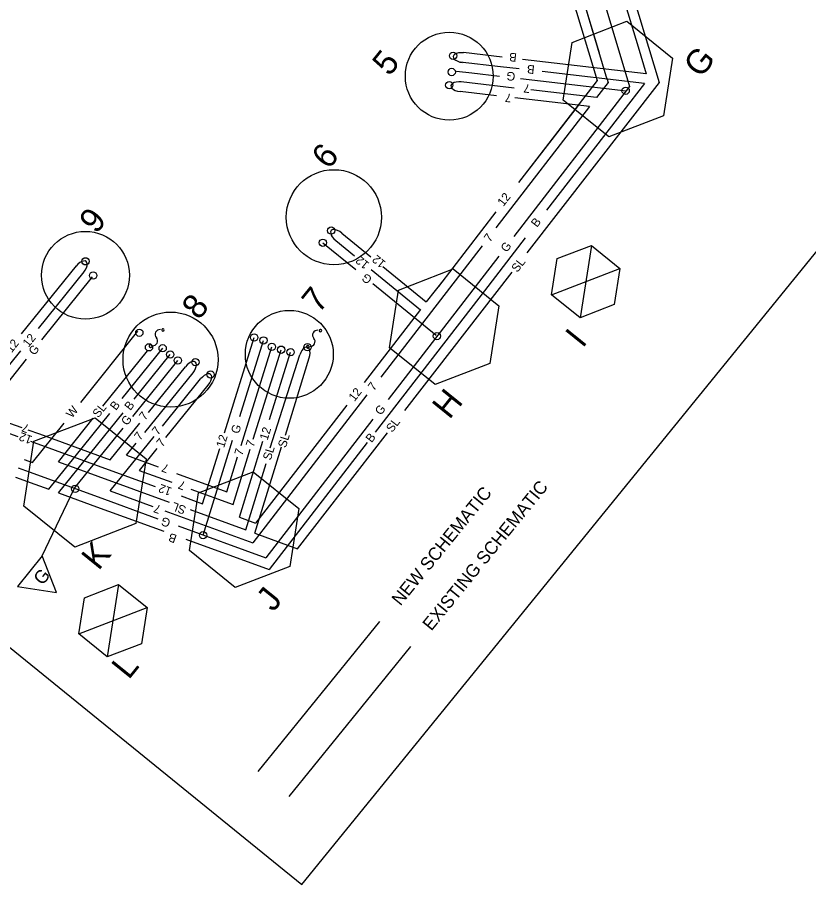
# Model space of a CAD drawing. Extents: x 592613 to 600223, y 4837996 to 4840103.
# Drawn here: x 592751.79 to 592782.58, y 4838886.03 to 4838919.81 of the extents above; entities that cross this region are included whole.
import ezdxf

# ---------------------------------------------------------------- set-up
doc = ezdxf.new("R2010")
doc.units = 0
for name, color, linetype in [('ENG_BORDER', 7, 'Continuous'), ('TCS_ELEC-CHAMBER-NEW', 7, 'Continuous'), ('TCS_FUSE', 7, 'Continuous'), ('TCS_PLATE', 7, 'Continuous'), ('TCS_POLE-NEW', 7, 'Continuous'), ('TCS_TX_LEGEND', 7, 'Continuous'), ('TCS_WR_12', 7, 'Continuous'), ('TCS_WR_7', 7, 'Continuous'), ('TCS_WR_B', 7, 'Continuous'), ('TCS_WR_G', 7, 'Continuous'), ('TCS_WR_SL', 7, 'Continuous'), ('TCS_WR_W', 7, 'Continuous'), ('TCS_WR_W-EXIST', 7, 'Continuous')]:
    doc.layers.add(name, color=color, linetype=linetype)

msp = doc.modelspace()

# ---------------------------------------------------------------- linework, layer by layer
at = {"layer": 'ENG_BORDER'}
for points in [[(592762.862, 4838886.033), (592888.241, 4839040.345), (592783.858, 4839125.156)], [(592658.479, 4838970.843), (592762.862, 4838886.033)]]:
    msp.add_lwpolyline(points, dxfattribs=at)
at = {"layer": 'TCS_ELEC-CHAMBER-NEW'}
for p, q in [((592773.377, 4838918.834), (592775.504, 4838919.654)), ((592775.504, 4838919.654), (592777.278, 4838918.222)), ((592773.023, 4838916.582), (592773.377, 4838918.834)), ((592777.278, 4838918.222), (592776.924, 4838915.969)), ((592774.797, 4838915.149), (592773.023, 4838916.582)), ((592776.924, 4838915.969), (592774.797, 4838915.149)), ((592772.794, 4838910.413), (592774.123, 4838910.925)), ((592774.123, 4838910.925), (592773.681, 4838908.11)), ((592774.123, 4838910.925), (592775.232, 4838910.03)), ((592772.573, 4838909.005), (592772.794, 4838910.413)), ((592766.624, 4838909.189), (592768.751, 4838910.009)), ((592768.751, 4838910.009), (592770.525, 4838908.577)), ((592772.573, 4838909.005), (592775.232, 4838910.03)), ((592775.232, 4838910.03), (592775.011, 4838908.622)), ((592766.27, 4838906.937), (592766.624, 4838909.189)), ((592773.681, 4838908.11), (592772.573, 4838909.005)), ((592770.525, 4838908.577), (592770.171, 4838906.324)), ((592775.011, 4838908.622), (592773.681, 4838908.11)), ((592768.044, 4838905.505), (592766.27, 4838906.937)), ((592770.171, 4838906.324), (592768.044, 4838905.505)), ((592752.432, 4838903.298), (592754.813, 4838904.216)), ((592754.813, 4838904.216), (592756.798, 4838902.613)), ((592752.036, 4838900.778), (592752.432, 4838903.298)), ((592756.798, 4838902.613), (592756.402, 4838900.092)), ((592758.84, 4838901.293), (592760.968, 4838902.113)), ((592760.968, 4838902.113), (592762.741, 4838900.681)), ((592758.487, 4838899.041), (592758.84, 4838901.293)), ((592754.021, 4838899.175), (592752.036, 4838900.778)), ((592762.741, 4838900.681), (592762.388, 4838898.428)), ((592756.402, 4838900.092), (592754.021, 4838899.175)), ((592760.26, 4838897.609), (592758.487, 4838899.041)), ((592762.388, 4838898.428), (592760.26, 4838897.609)), ((592754.397, 4838897.205), (592755.727, 4838897.717)), ((592755.727, 4838897.717), (592755.284, 4838894.902)), ((592755.727, 4838897.717), (592756.835, 4838896.822)), ((592754.176, 4838895.797), (592754.397, 4838897.205)), ((592754.176, 4838895.797), (592756.835, 4838896.822)), ((592756.835, 4838896.822), (592756.614, 4838895.414)), ((592755.284, 4838894.902), (592754.176, 4838895.797)), ((592756.614, 4838895.414), (592755.284, 4838894.902))]:
    msp.add_line(p, q, dxfattribs=at)
at = {"layer": 'TCS_FUSE'}
for centre, radius, start, end in [((592757.337, 4838907.46), 0.189, 85.1625, 221.8112), ((592757.452, 4838907.634), 0.0513, 44.5286, 224.5286), ((592757.452, 4838907.634), 0.0513, 224.5286, 44.5286), ((592763.464, 4838907.434), 0.189, 85.1625, 221.8112), ((592763.579, 4838907.609), 0.0513, 44.5286, 224.5286), ((592763.579, 4838907.609), 0.0513, 224.5286, 44.5286), ((592757.056, 4838907.208), 0.189, 265.1625, 41.8112), ((592763.182, 4838907.182), 0.189, 265.1625, 41.8112), ((592756.965, 4838907.007), 0.0513, 44.5286, 224.5286), ((592756.965, 4838907.007), 0.0513, 224.5286, 44.5286), ((592763.091, 4838906.981), 0.0513, 44.5286, 224.5286), ((592763.091, 4838906.981), 0.0513, 224.5286, 44.5286)]:
    msp.add_arc(centre, radius, start, end, dxfattribs=at)
at = {"layer": 'TCS_PLATE'}
for p, q in [((592752.755, 4838898.841), (592751.788, 4838897.644)), ((592753.308, 4838897.406), (592752.755, 4838898.841)), ((592751.788, 4838897.644), (592753.308, 4838897.406))]:
    msp.add_line(p, q, dxfattribs=at)
at = {"layer": 'TCS_POLE-NEW'}
for centre, radius in [((592768.594, 4838917.516), 1.71), ((592764.103, 4838912.025), 1.851), ((592754.435, 4838909.763), 1.71), ((592757.748, 4838906.481), 1.85), ((592762.368, 4838906.685), 1.71)]:
    msp.add_circle(centre, radius, dxfattribs=at)
at = {"layer": 'TCS_WR_12'}
for p, q in [((592773.045, 4838921.693), (592774.353, 4838917.343)), ((592774.353, 4838917.343), (592771.292, 4838913.376)), ((592773.611, 4838916.382), (592771.292, 4838913.376)), ((592770.411, 4838912.234), (592768.171, 4838909.331)), ((592764.413, 4838911.41), (592765.543, 4838910.488)), ((592764.173, 4838911.116), (592764.906, 4838910.517)), ((592751.952, 4838907.477), (592754.083, 4838910.135)), ((592752.61, 4838907.69), (592754.38, 4838909.897)), ((592765.56, 4838909.983), (592767.471, 4838908.423)), ((592766.014, 4838910.102), (592767.701, 4838908.726)), ((592768.39, 4838909.614), (592767.701, 4838908.726)), ((592767.472, 4838908.425), (592765.283, 4838905.588)), ((592759.852, 4838903.629), (592761.004, 4838907.342)), ((592749.819, 4838904.21), (592751.916, 4838906.824)), ((592761.604, 4838904.148), (592762.419, 4838906.772)), ((592764.605, 4838904.709), (592761.059, 4838900.113)), ((592749.818, 4838904.209), (592751.806, 4838903.484)), ((592752.301, 4838903.304), (592755.314, 4838902.206)), ((592760.426, 4838900.344), (592761.343, 4838903.307)), ((592758.993, 4838900.866), (592759.663, 4838903.021)), ((592755.314, 4838902.206), (592757.149, 4838901.538)), ((592758.157, 4838901.17), (592758.636, 4838900.996)), ((592758.636, 4838900.996), (592758.993, 4838900.866)), ((592760.426, 4838900.344), (592761.059, 4838900.113))]:
    msp.add_line(p, q, dxfattribs=at)
for centre, major_axis in [((592764.293, 4838911.263), (0.294, -0.24)), ((592754.225, 4838910.005), (-0.24, -0.294))]:
    msp.add_ellipse(centre, major_axis=major_axis, ratio=0.5, start_param=1.570796, end_param=4.712389, dxfattribs=at)
at = {"layer": 'TCS_WR_7'}
for p, q in [((592773.154, 4838922.649), (592774.425, 4838918.421)), ((592773.154, 4838922.649), (592774.731, 4838917.405)), ((592771.118, 4838917.056), (592769.059, 4838917.293)), ((592774.773, 4838917.265), (592774.327, 4838916.687)), ((592774.72, 4838917.44), (592774.773, 4838917.265)), ((592770.426, 4838916.753), (592769.015, 4838916.915)), ((592774.327, 4838916.687), (592771.767, 4838916.981)), ((592774.056, 4838916.336), (592771.151, 4838916.67)), ((592774.056, 4838916.336), (592770.409, 4838911.609)), ((592769.871, 4838910.912), (592765.928, 4838905.802)), ((592760.898, 4838904.437), (592761.689, 4838906.979)), ((592761.261, 4838904.324), (592762.052, 4838906.866)), ((592756.883, 4838904.415), (592758.328, 4838906.204)), ((592756.75, 4838903.646), (592758.623, 4838905.965)), ((592757.431, 4838903.885), (592758.919, 4838905.726)), ((592757.566, 4838903.446), (592759.215, 4838905.487)), ((592765.391, 4838905.105), (592760.946, 4838899.345)), ((592760.494, 4838903.135), (592760.898, 4838904.437)), ((592760.967, 4838903.378), (592761.261, 4838904.324)), ((592751.485, 4838904.005), (592751.955, 4838903.834)), ((592752.191, 4838903.748), (592752.644, 4838903.583)), ((592755.4, 4838902.579), (592756.556, 4838904.011)), ((592752.644, 4838903.583), (592755.4, 4838902.579)), ((592755.397, 4838901.367), (592757.106, 4838903.482)), ((592756.03, 4838902.754), (592756.411, 4838903.227)), ((592756.03, 4838902.754), (592757.266, 4838902.304)), ((592757.218, 4838903.017), (592756.532, 4838902.167)), ((592759.934, 4838901.332), (592760.357, 4838902.694)), ((592760.179, 4838900.838), (592760.849, 4838902.996)), ((592756.532, 4838902.167), (592757.793, 4838901.708)), ((592757.982, 4838902.043), (592759.934, 4838901.332)), ((592755.397, 4838901.367), (592757.055, 4838900.763)), ((592758.541, 4838901.435), (592760.179, 4838900.838)), ((592757.523, 4838900.593), (592760.946, 4838899.345))]:
    msp.add_line(p, q, dxfattribs=at)
for centre, major_axis in [((592769.037, 4838917.104), (0.377, -0.044)), ((592758.476, 4838906.084), (-0.239, -0.296)), ((592759.067, 4838905.607), (-0.239, -0.296))]:
    msp.add_ellipse(centre, major_axis=major_axis, ratio=0.5, start_param=1.570796, end_param=4.712389, dxfattribs=at)
at = {"layer": 'TCS_WR_B'}
for p, q in [((592774.328, 4838924.034), (592775.942, 4838918.661)), ((592775.942, 4838918.661), (592776.258, 4838917.611)), ((592770.655, 4838918.259), (592769.15, 4838918.434)), ((592770.585, 4838917.885), (592769.013, 4838918.067)), ((592776.258, 4838917.611), (592771.446, 4838918.168)), ((592771.32, 4838917.8), (592770.585, 4838917.885)), ((592776.19, 4838917.236), (592772.209, 4838917.697)), ((592776.19, 4838917.236), (592775.352, 4838916.148)), ((592775.352, 4838916.148), (592772.377, 4838912.293)), ((592771.55, 4838911.221), (592769.959, 4838909.16)), ((592769.959, 4838909.16), (592765.715, 4838903.66)), ((592755.862, 4838904.966), (592757.441, 4838906.92)), ((592756.328, 4838904.938), (592757.737, 4838906.681)), ((592753.383, 4838901.292), (592755.904, 4838904.412)), ((592753.005, 4838901.43), (592755.385, 4838904.375)), ((592765.396, 4838903.246), (592761.583, 4838898.304)), ((592751.712, 4838901.901), (592752.467, 4838901.626)), ((592752.467, 4838901.626), (592753.005, 4838901.43)), ((592753.383, 4838901.292), (592754.866, 4838900.752)), ((592754.866, 4838900.752), (592757.488, 4838899.796)), ((592758.336, 4838899.487), (592761.583, 4838898.304))]:
    msp.add_line(p, q, dxfattribs=at)
msp.add_ellipse((592769.128, 4838918.239), major_axis=(0.377, -0.044), ratio=0.5, start_param=1.570796, end_param=4.712389, dxfattribs=at)
at = {"layer": 'TCS_WR_G'}
for p, q in [((592773.648, 4838923.644), (592775.613, 4838917.11)), ((592769.475, 4838917.631), (592768.871, 4838917.701)), ((592770.542, 4838917.507), (592769.475, 4838917.631)), ((592775.472, 4838916.936), (592771.359, 4838917.413)), ((592775.613, 4838917.11), (592771.106, 4838911.268)), ((592763.676, 4838911.031), (592764.952, 4838909.989)), ((592770.518, 4838910.506), (592766.21, 4838904.923)), ((592752.742, 4838907.251), (592754.705, 4838909.699)), ((592765.619, 4838909.444), (592768.084, 4838907.431)), ((592760.445, 4838904.259), (592761.367, 4838907.229)), ((592749.701, 4838903.459), (592752.14, 4838906.5)), ((592756.276, 4838904.268), (592758.032, 4838906.442)), ((592765.622, 4838904.161), (592761.452, 4838898.756)), ((592754.012, 4838901.467), (592755.902, 4838903.806)), ((592759.013, 4838899.645), (592760.159, 4838903.34)), ((592751.821, 4838902.266), (592752.244, 4838902.112)), ((592752.244, 4838902.112), (592754.933, 4838901.132)), ((592752.751, 4838898.841), (592753.991, 4838901.444)), ((592754.933, 4838901.132), (592757.258, 4838900.285)), ((592758.038, 4838900.001), (592761.452, 4838898.756))]:
    msp.add_line(p, q, dxfattribs=at)
at = {"layer": 'TCS_WR_SL'}
for p, q in [((592774.982, 4838923.176), (592776.758, 4838917.268)), ((592776.758, 4838917.268), (592771.615, 4838910.638)), ((592771.031, 4838909.885), (592766.852, 4838904.498)), ((592755.11, 4838904.662), (592756.851, 4838906.823)), ((592761.63, 4838903.05), (592762.782, 4838906.66)), ((592762.218, 4838903.538), (592763.145, 4838906.547)), ((592753.383, 4838902.505), (592754.738, 4838904.203)), ((592766.174, 4838903.623), (592762.673, 4838899.11)), ((592761.029, 4838899.72), (592762.069, 4838903.083)), ((592753.383, 4838902.505), (592754.915, 4838901.947)), ((592760.671, 4838899.85), (592761.472, 4838902.439)), ((592754.915, 4838901.947), (592757.697, 4838900.934)), ((592758.506, 4838900.639), (592760.671, 4838899.85)), ((592761.029, 4838899.72), (592762.689, 4838899.115))]:
    msp.add_line(p, q, dxfattribs=at)
msp.add_ellipse((592762.963, 4838906.603), major_axis=(-0.113, -0.363), ratio=0.5, start_param=1.570796, end_param=4.712389, dxfattribs=at)
at = {"layer": 'TCS_WR_W'}
for p, q in [((592754.254, 4838904.811), (592756.477, 4838907.584)), ((592752.375, 4838902.468), (592753.607, 4838904.005)), ((592752.056, 4838902.585), (592752.374, 4838902.469)), ((592761.157, 4838890.444), (592765.898, 4838896.279))]:
    msp.add_line(p, q, dxfattribs=at)
for centre, radius in [((592768.741, 4838918.311), 0.143), ((592768.689, 4838917.68), 0.143), ((592768.594, 4838917.17), 0.143), ((592775.457, 4838916.95), 0.142), ((592763.999, 4838911.503), 0.142), ((592763.676, 4838911.031), 0.142), ((592754.436, 4838910.307), 0.142), ((592754.734, 4838909.754), 0.142), ((592756.532, 4838907.526), 0.142), ((592761.004, 4838907.342), 0.142), ((592768.114, 4838907.397), 0.142), ((592756.909, 4838906.958), 0.142), ((592761.367, 4838907.229), 0.142), ((592761.689, 4838906.979), 0.142), ((592763.076, 4838906.966), 0.142), ((592757.441, 4838906.92), 0.142), ((592757.737, 4838906.681), 0.142), ((592762.052, 4838906.866), 0.142), ((592762.419, 4838906.772), 0.142), ((592758.032, 4838906.442), 0.142), ((592758.714, 4838906.38), 0.142), ((592759.306, 4838905.902), 0.142), ((592754.036, 4838901.445), 0.142), ((592759.013, 4838899.645), 0.142)]:
    msp.add_circle(centre, radius, dxfattribs=at)
at = {"layer": 'TCS_WR_W-EXIST'}
msp.add_line((592762.358, 4838889.468), (592767.099, 4838895.303), dxfattribs=at)

# ---------------------------------------------------------------- texts
at = {"layer": 'TCS_ELEC-CHAMBER-NEW'}
for s, p in [('G', (592778.379, 4838917.411)), ('I', (592773.78, 4838906.898)), ('H', (592768.597, 4838904.118)), ('K', (592754.945, 4838898.235)), ('J', (592761.746, 4838896.623)), ('L', (592756.119, 4838893.986))]:
    msp.add_text(s, height=0.95, rotation=51.0744, dxfattribs=at).set_placement(p)
at = {"layer": 'TCS_PLATE'}
msp.add_text('G', height=0.513, rotation=51.0744, dxfattribs=at).set_placement((592752.766, 4838897.662))
at = {"layer": 'TCS_POLE-NEW'}
for s, p in [('5', (592766.263, 4838917.482)), ('6', (592763.902, 4838913.852)), ('9', (592754.857, 4838911.343)), ('7', (592763.517, 4838908.249)), ('8', (592758.847, 4838907.988))]:
    msp.add_text(s, height=0.95, rotation=51.0744, dxfattribs=at).set_placement(p)
at = {"layer": 'TCS_TX_LEGEND'}
for s, p in [('EXISTING SCHEMATIC', (592767.897, 4838895.888)), ('NEW SCHEMATIC', (592766.695, 4838896.864))]:
    msp.add_text(s, height=0.5, rotation=50.9061, dxfattribs=at).set_placement(p)
at = {"layer": 'TCS_WR_12'}
for rotation, p in [(52.3474, (592770.7, 4838912.423)), (140.77, (592765.506, 4838910.226)), (140.77, (592766.15, 4838910.269)), (51.273, (592752.219, 4838906.937)), (51.273, (592751.561, 4838906.724)), (52.3474, (592764.906, 4838904.827)), (72.7522, (592761.52, 4838903.317)), (159.9803, (592752.394, 4838903.488)), (72.7522, (592759.829, 4838903.023)), (159.9803, (592757.824, 4838901.476))]:
    msp.add_text('12', height=0.3325, rotation=rotation, dxfattribs=at).set_placement(p)
at = {"layer": 'TCS_WR_7'}
for height, rotation, p in [(0.332, 173.3942, (592771.753, 4838917.188)), (0.332, 173.3942, (592771.033, 4838916.82)), (0.333, 52.3474, (592770.174, 4838911.033)), (0.333, 52.3474, (592765.659, 4838905.242)), (0.332, 52.0235, (592756.753, 4838904.091)), (0.333, 159.9803, (592752.274, 4838903.923)), (0.332, 52.0235, (592757.256, 4838903.515)), (0.332, 52.0235, (592756.564, 4838903.306)), (0.332, 52.0235, (592757.428, 4838903.053)), (0.332, 72.7522, (592760.981, 4838903.05)), (0.332, 72.7522, (592760.537, 4838902.72)), (0.333, 159.9803, (592757.713, 4838902.361)), (0.333, 159.9803, (592758.358, 4838901.695)), (0.333, 159.9803, (592757.405, 4838900.777))]:
    msp.add_text('7', height=height, rotation=rotation, dxfattribs=at).set_placement(p)
at = {"layer": 'TCS_WR_B'}
for height, rotation, p in [(0.332, 173.3942, (592771.235, 4838918.401)), (0.332, 173.3942, (592771.931, 4838917.929)), (0.332, 52.3474, (592772.006, 4838911.608)), (0.332, 52.0235, (592755.622, 4838904.478)), (0.332, 52.0235, (592756.183, 4838904.474)), (0.332, 52.3474, (592765.571, 4838903.224)), (0.333, 159.9803, (592758.019, 4838899.635))]:
    msp.add_text('B', height=height, rotation=rotation, dxfattribs=at).set_placement(p)
at = {"layer": 'TCS_WR_G'}
for height, rotation, p in [(0.333, 173.3942, (592771.179, 4838917.658)), (0.332, 52.3474, (592770.826, 4838910.634)), (0.333, 140.77, (592765.621, 4838909.648)), (0.333, 51.273, (592752.451, 4838906.622)), (0.332, 52.3474, (592765.931, 4838904.289)), (0.332, 52.0235, (592756.055, 4838903.886)), (0.333, 72.7522, (592760.404, 4838903.567)), (0.333, 159.9803, (592757.777, 4838900.244))]:
    msp.add_text('G', height=height, rotation=rotation, dxfattribs=at).set_placement(p)
at = {"layer": 'TCS_WR_SL'}
for rotation, p in [(52.3474, (592771.245, 4838909.854)), (51.273, (592754.937, 4838904.191)), (52.3474, (592766.369, 4838903.62)), (72.7522, (592762.232, 4838903.023)), (72.7522, (592761.644, 4838902.535)), (159.9803, (592758.382, 4838900.751))]:
    msp.add_text('SL', height=0.3325, rotation=rotation, dxfattribs=at).set_placement(p)
at = {"layer": 'TCS_WR_W'}
msp.add_text('W', height=0.333, rotation=51.273, dxfattribs=at).set_placement((592753.913, 4838904.178))

doc.saveas('drawing.dxf')
